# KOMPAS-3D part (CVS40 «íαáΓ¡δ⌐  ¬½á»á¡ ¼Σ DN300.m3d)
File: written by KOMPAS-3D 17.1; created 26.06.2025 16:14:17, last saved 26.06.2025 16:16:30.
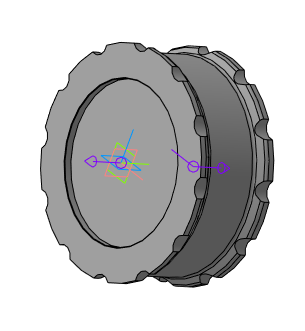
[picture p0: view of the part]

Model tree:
1. Эскиз:1
2. Элемент вращения:1
     Угол 1 = 360
3. Присоединительная точка:1
4. Присоединительная точка:2
5. Эскиз:2
6. Элемент выдавливания:1
     Расстояние 2 = 160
